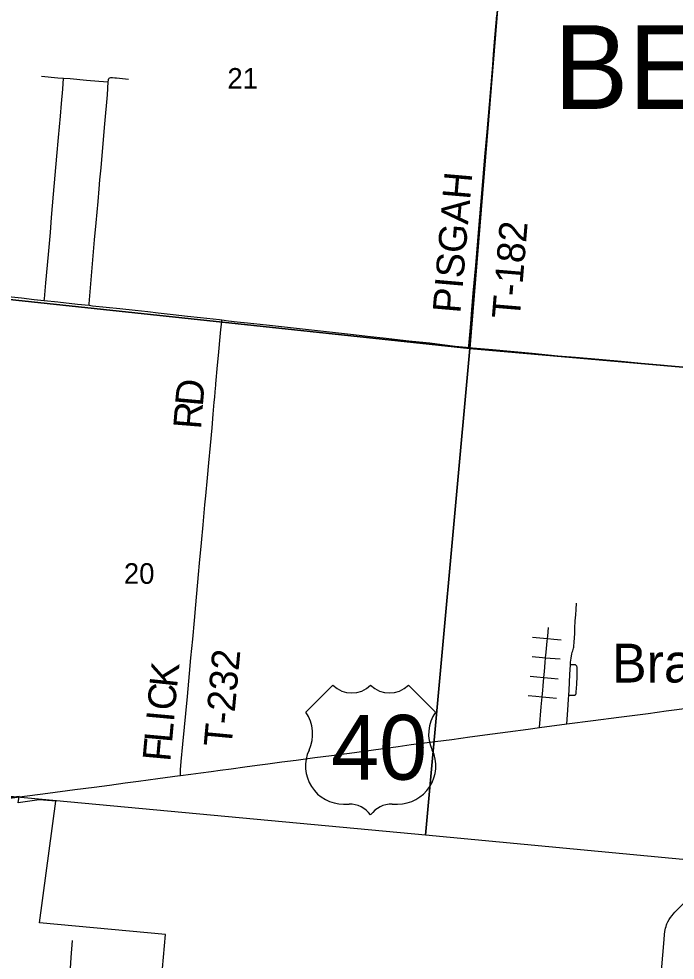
# Model space of a CAD drawing. Extents: x -38.1 to 35.9, y -2.7 to 28.5.
# Drawn here: x 12.272 to 13.609, y 15.8 to 17.716 of the extents above; entities that cross this region are included whole.
import ezdxf

# ---------------------------------------------------------------- set-up
doc = ezdxf.new("R2010")
doc.units = 0
for name, color, linetype in [('GM_P_County_Alignment', 7, 'Continuous'), ('GM_X_City_Street', 7, 'Continuous'), ('GM_X_City_Street_Text', 7, 'Continuous'), ('GM_X_County_Road', 7, 'Continuous'), ('GM_X_Interstate_Location', 7, 'Continuous'), ('GM_X_Major_River', 7, 'Continuous'), ('GM_X_Major_River_Text', 7, 'Continuous'), ('GM_X_Minor_Lake', 7, 'Continuous'), ('GM_X_Minor_River', 7, 'Continuous'), ('GM_X_Township_Subdivision_Text', 7, 'Continuous'), ('GM_X_US_Route', 7, 'Continuous')]:
    doc.layers.add(name, color=color, linetype=linetype)

msp = doc.modelspace()

# ---------------------------------------------------------------- linework, layer by layer
at = {"layer": 'GM_X_City_Street'}
msp.add_lwpolyline([(12.4157, 15.6343), (12.4162, 15.6432), (12.4157, 15.6541), (12.4112, 15.6679), (12.4051, 15.6834), (12.3959, 15.7036), (12.3841, 15.7313), (12.3806, 15.7414), (12.3782, 15.7534), (12.3767, 15.7673), (12.3777, 15.7825), (12.3792, 15.805), (12.3819, 15.84)], dxfattribs=at)
at = {"layer": 'GM_X_City_Street_Text'}
for points in [[(11.6635, 17.2042), (11.6658, 17.204), (11.719, 17.1992), (11.7718, 17.1946), (11.8019, 17.1918), (11.8297, 17.1894), (11.8594, 17.1866), (11.8891, 17.184), (11.9275, 17.1807), (11.9789, 17.1762), (12.0228, 17.1722), (12.0507, 17.1697), (12.0841, 17.1667), (12.1113, 17.1642), (12.1379, 17.1618), (12.1725, 17.1585), (12.196, 17.1562), (12.2207, 17.1537), (12.251, 17.1504), (12.2778, 17.1474), (12.3036, 17.1446), (12.3242, 17.1423)], [(12.3242, 17.1423), (12.3518, 17.1393), (12.3918, 17.1351), (12.4154, 17.1325)], [(12.4154, 17.1325), (12.4227, 17.1317), (12.4783, 17.126), (12.5092, 17.1227), (12.5351, 17.1198), (12.5561, 17.1174), (12.5865, 17.114), (12.616, 17.1107), (12.6425, 17.1076), (12.6808, 17.1033), (12.686, 17.1027)], [(12.686, 17.1027), (12.6995, 17.1012), (12.7172, 17.0992), (12.738, 17.0969), (12.7765, 17.0927), (12.8198, 17.088), (12.8562, 17.084), (12.9235, 17.0765), (12.9543, 17.073), (12.9828, 17.0697), (13.0204, 17.0655), (13.0668, 17.0605), (13.1094, 17.0558), (13.1402, 17.052), (13.1611, 17.0495), (13.1834, 17.047), (13.1883, 17.0466)], [(13.1883, 17.0466), (13.2373, 17.0423), (13.3177, 17.0348), (13.3703, 17.03), (13.4062, 17.0268), (13.4539, 17.0227), (13.4991, 17.0187), (13.5401, 17.0148), (13.5789, 17.0113), (13.6086, 17.0086), (13.6326, 17.0064)]]:
    msp.add_lwpolyline(points, dxfattribs=at)
at = {"layer": 'GM_X_Interstate_Location'}
for p, q in [((12.912, 16.3592), (12.857, 16.3043)), ((13.1207, 16.3043), (13.0658, 16.3592)), ((12.9339, 16.1175), (12.9449, 16.1175)), ((13.0328, 16.1175), (13.0438, 16.1175))]:
    msp.add_line(p, q, dxfattribs=at)
for centre, radius, start, end in [((12.9504, 16.3984), 0.0549, 225.573, 314.427), ((13.0273, 16.3984), 0.0549, 225.573, 314.427), ((12.794, 16.2602), 0.0769, 334.5471, 35.0009), ((13.1837, 16.2602), 0.0769, 144.9991, 205.4529), ((12.9331, 16.1944), 0.0769, 154.8319, 270.6383), ((13.0447, 16.1944), 0.0769, 269.3617, 25.1681), ((12.9449, 16.0626), 0.0549, 36.8699, 90), ((13.0328, 16.0626), 0.0549, 90, 143.1301)]:
    msp.add_arc(centre, radius, start, end, dxfattribs=at)
at = {"layer": 'GM_X_Major_River'}
for points in [[(13.5909, 16.3069), (13.6069, 16.3091), (13.6591, 16.3161), (13.7098, 16.3224), (13.7399, 16.3264), (13.7637, 16.3295), (13.7956, 16.3337), (13.8263, 16.3378), (13.868, 16.3435), (13.8832, 16.3456), (13.9104, 16.3495), (13.9523, 16.3552), (13.9691, 16.3575), (13.9921, 16.3605), (14.0387, 16.3668), (14.0556, 16.3689), (14.0791, 16.372), (14.1023, 16.375), (14.1274, 16.3783), (14.1545, 16.3818), (14.1621, 16.3829)], [(12.2735, 16.132), (12.3317, 16.1396), (12.3865, 16.1468), (12.4256, 16.1517), (12.4569, 16.1557), (12.4893, 16.1605), (12.5164, 16.1641), (12.5558, 16.1693), (12.6001, 16.1752), (12.6017, 16.1754), (12.6229, 16.1781), (12.6428, 16.1808), (12.6639, 16.1837), (12.6826, 16.1863), (12.7047, 16.1893), (12.7324, 16.193), (12.7579, 16.1964), (12.7798, 16.1994), (12.8079, 16.2032), (12.8371, 16.207), (12.875, 16.2119), (12.909, 16.2163), (12.956, 16.2225), (12.9948, 16.2279), (13.0446, 16.2347), (13.0717, 16.2385), (13.1204, 16.2449), (13.1543, 16.2491), (13.1912, 16.2539), (13.2368, 16.2602), (13.2683, 16.2642), (13.31, 16.2698), (13.3327, 16.2729), (13.3885, 16.2804), (13.4418, 16.2874), (13.4941, 16.2942), (13.5539, 16.3019), (13.5909, 16.3069)], [(12.0949, 16.1084), (12.1179, 16.1115), (12.1444, 16.115), (12.1826, 16.1202), (12.2179, 16.1248), (12.2491, 16.1289), (12.2735, 16.132)]]:
    msp.add_lwpolyline(points, dxfattribs=at)
at = {"layer": 'GM_X_Major_River_Text'}
for points in [[(13.1883, 17.0466), (13.1886, 17.0497), (13.1908, 17.0726), (13.1928, 17.0955), (13.1951, 17.1235), (13.198, 17.1575), (13.2028, 17.2137), (13.2092, 17.2891), (13.2155, 17.3604), (13.2217, 17.4345), (13.2261, 17.4858), (13.2335, 17.5734), (13.2374, 17.6217), (13.2392, 17.6427), (13.2419, 17.6768), (13.2461, 17.7232)], [(12.3184, 17.5986), (12.3517, 17.5958), (12.3637, 17.5949)], [(12.3242, 17.1423), (12.3245, 17.1459), (12.3275, 17.1785), (12.3326, 17.236), (12.3366, 17.2805), (12.3392, 17.3115), (12.3433, 17.3585), (12.3501, 17.4358), (12.3533, 17.4742), (12.3572, 17.5175), (12.3593, 17.5435), (12.3619, 17.5726), (12.3637, 17.5949)], [(12.3637, 17.5949), (12.3771, 17.5938), (12.4104, 17.5908), (12.4352, 17.589), (12.4546, 17.5874)], [(12.4546, 17.5874), (12.4549, 17.5909), (12.4553, 17.5927), (12.4556, 17.5936), (12.4565, 17.5949), (12.4579, 17.5957), (12.46, 17.5961), (12.4634, 17.596), (12.4682, 17.5957), (12.4716, 17.5953), (12.4958, 17.593)], [(12.4154, 17.1325), (12.4156, 17.1355), (12.4268, 17.2655), (12.43, 17.3002), (12.4337, 17.3441), (12.4359, 17.3695), (12.4375, 17.3881), (12.4398, 17.4122), (12.4447, 17.4698), (12.4476, 17.502), (12.4527, 17.5608), (12.4546, 17.5874)], [(12.6017, 16.1754), (12.6016, 16.1793), (12.6015, 16.1812), (12.6016, 16.1836), (12.6019, 16.1868), (12.6033, 16.2041), (12.6066, 16.2392), (12.6156, 16.3365), (12.6201, 16.3833), (12.6229, 16.4149), (12.6265, 16.4532), (12.6299, 16.4909), (12.6328, 16.5231), (12.6383, 16.5843), (12.6405, 16.6079), (12.6443, 16.6491), (12.6475, 16.6855), (12.6513, 16.7264), (12.6532, 16.7449), (12.6565, 16.7813), (12.6593, 16.8116), (12.6626, 16.8469), (12.6659, 16.8834), (12.6682, 16.9111), (12.6703, 16.9352), (12.6713, 16.9457), (12.6722, 16.9562), (12.6734, 16.9698), (12.6737, 16.9728), (12.6773, 17.011), (12.6789, 17.0302), (12.6831, 17.0759), (12.6839, 17.0831), (12.6856, 17.0991), (12.686, 17.1027)], [(13.3885, 16.2804), (13.3905, 16.3087), (13.392, 16.331), (13.3924, 16.3391), (13.3929, 16.3491), (13.3948, 16.3808), (13.3959, 16.4009), (13.3962, 16.4062), (13.397, 16.4143), (13.3976, 16.4188), (13.3984, 16.4227), (13.3993, 16.4264), (13.4003, 16.4292), (13.4013, 16.4319), (13.4021, 16.4344), (13.4025, 16.4365), (13.403, 16.439), (13.4035, 16.4466), (13.4045, 16.4643), (13.4049, 16.4755), (13.4057, 16.4904), (13.4064, 16.5023), (13.4072, 16.5137), (13.4082, 16.5264)], [(13.3327, 16.2729), (13.3364, 16.3155), (13.3382, 16.3358), (13.3394, 16.3487), (13.3402, 16.358), (13.3417, 16.375), (13.3428, 16.3875), (13.3443, 16.4055), (13.3452, 16.4151), (13.3462, 16.4267), (13.3484, 16.4489), (13.3489, 16.4541), (13.3494, 16.4593), (13.3509, 16.4768)], [(13.3183, 16.4569), (13.341, 16.4549), (13.3489, 16.4541), (13.3618, 16.453), (13.377, 16.4516)], [(13.3178, 16.4174), (13.3388, 16.4156), (13.3452, 16.4151), (13.3548, 16.4143), (13.3746, 16.4128)], [(13.3924, 16.3391), (13.3958, 16.339), (13.4021, 16.3388), (13.4033, 16.3389), (13.4045, 16.3391), (13.4052, 16.3394), (13.406, 16.3399), (13.4065, 16.3405), (13.4069, 16.3412), (13.4072, 16.3421), (13.4074, 16.3433), (13.4076, 16.345), (13.4085, 16.3617), (13.4093, 16.3772), (13.4096, 16.3885), (13.4096, 16.3922), (13.4095, 16.3951), (13.4093, 16.3962), (13.4091, 16.3971), (13.4087, 16.3979), (13.4083, 16.3986), (13.4077, 16.3994), (13.4069, 16.4), (13.4064, 16.4003), (13.4058, 16.4005), (13.4049, 16.4008), (13.404, 16.4009), (13.4027, 16.4009), (13.3959, 16.4009)], [(13.3136, 16.3775), (13.3273, 16.3763), (13.3417, 16.375), (13.3563, 16.3737), (13.3709, 16.3725)], [(13.3095, 16.3381), (13.3256, 16.3369), (13.3382, 16.3358), (13.3528, 16.3344), (13.3676, 16.3331)], [(13.5791, 15.7543), (13.5864, 15.8416), (13.5874, 15.852), (13.5882, 15.8583), (13.5887, 15.8612), (13.5896, 15.8651), (13.5905, 15.8684), (13.5915, 15.8717), (13.5923, 15.8738), (13.5942, 15.8779), (13.5967, 15.8824), (13.5996, 15.8866), (13.6026, 15.8904), (13.6049, 15.893), (13.6085, 15.8971), (13.6124, 15.9014), (13.6181, 15.9071), (13.6229, 15.9118), (13.6307, 15.9198), (13.6697, 15.9596), (13.6949, 15.9853), (13.7142, 16.0055), (13.7294, 16.0211), (13.7367, 16.0285)]]:
    msp.add_lwpolyline(points, dxfattribs=at)
at = {"layer": 'GM_X_US_Route'}
for points in [[(13.2752, 18.0746), (13.1908, 17.0449), (12.1826, 17.1517), (12.2713, 18.1647)], [(13.2752, 18.0746), (14.2779, 17.9561), (14.1898, 16.9568), (13.1908, 17.0449)], [(13.1908, 17.0449), (13.1005, 16.0538), (12.0859, 16.1484), (12.1826, 17.1517)], [(13.1908, 17.0449), (14.1898, 16.9568), (14.1055, 15.9588), (13.1005, 16.0538)]]:
    msp.add_lwpolyline(points, close=True, dxfattribs=at)
msp.add_lwpolyline([(12.5609, 15.7367), (12.5712, 15.8516), (12.3147, 15.8755), (12.3481, 16.123), (12.3137, 16.1259), (12.271, 16.1201), (12.2731, 16.133), (12.0913, 16.1088), (12.0834, 16.0256), (12.0422, 16.0293), (12.0437, 16.0454), (11.9701, 16.0524), (11.9744, 16.0939), (11.7561, 16.0665), (11.7566, 15.9376), (11.6928, 15.943), (11.6675, 15.6807)], dxfattribs=at)

# ---------------------------------------------------------------- texts
at = {"layer": 'GM_P_County_Alignment'}
for s in ['0', '/']:
    msp.add_text(s, height=0.000189, dxfattribs=at).set_placement((12.9888, 16.2318))
msp.add_text('40', height=0.000189, rotation=0, dxfattribs=at).set_placement((12.9497, 16.1926))
at = {"layer": 'GM_X_County_Road'}
msp.add_text('BETHEL', height=0.17045, rotation=0, dxfattribs=at).set_placement((13.3616, 17.5322))
at = {"layer": 'GM_X_Interstate_Location'}
msp.add_text('40', height=0.13184, dxfattribs=at).set_placement((12.908, 16.167))
at = {"layer": 'GM_X_Minor_Lake'}
for s, height, rotation, p in [('PISGAH', 0.05682, 85.0796, (13.1716, 17.1151)), ('T-182', 0.05682, 85.2312, (13.2923, 17.1034)), ('D', 0.0568, 84.9152, (12.647, 16.9255)), ('R', 0.0568, 85.3621, (12.6433, 16.8792)), ('T-232', 0.05682, 84.6886, (12.7054, 16.232)), ('K', 0.0568, 83.938, (12.5945, 16.3527)), ('C', 0.0568, 84.7587, (12.5902, 16.3064)), ('I', 0.0568, 84.7784, (12.5881, 16.2832)), ('L', 0.0568, 84.7865, (12.5843, 16.2409)), ('F', 0.0568, 84.7804, (12.5808, 16.2027))]:
    msp.add_text(s, height=height, rotation=rotation, dxfattribs=at).set_placement(p)
at = {"layer": 'GM_X_Minor_River'}
for s, p in [('21', (12.6972, 17.5735)), ('20', (12.4864, 16.5657))]:
    msp.add_text(s, height=0.04186, rotation=0, dxfattribs=at).set_placement(p)
at = {"layer": 'GM_X_Township_Subdivision_Text'}
msp.add_text('Brandt', height=0.07898, rotation=0, dxfattribs=at).set_placement((13.4805, 16.3648))

doc.saveas('drawing.dxf')
